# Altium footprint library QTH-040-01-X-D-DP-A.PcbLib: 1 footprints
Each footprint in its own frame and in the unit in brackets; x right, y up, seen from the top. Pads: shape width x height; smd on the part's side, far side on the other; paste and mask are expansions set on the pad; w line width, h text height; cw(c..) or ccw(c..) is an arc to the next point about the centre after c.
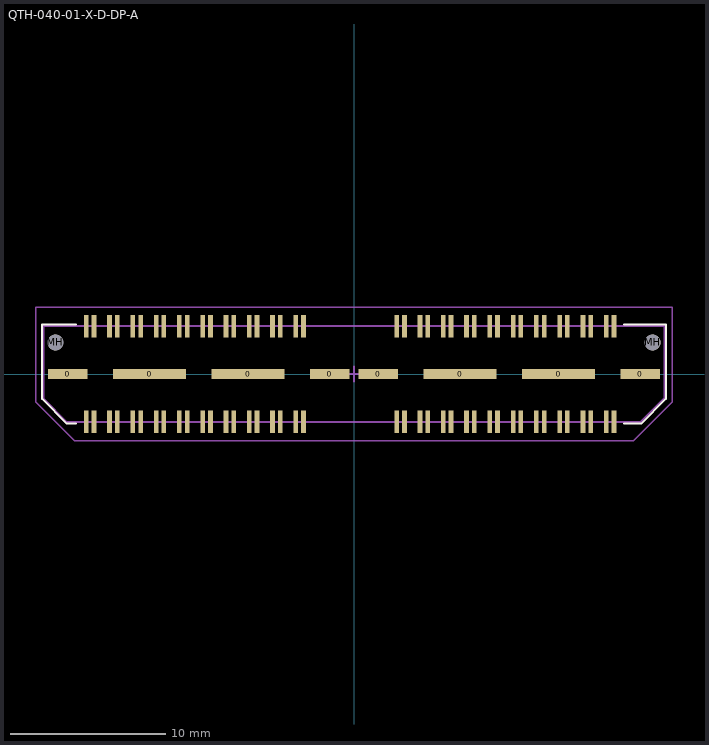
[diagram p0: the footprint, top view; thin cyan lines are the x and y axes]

## QTH-040-01-X-D-DP-A [mm] "0.5mm hi-speed, high-density header (female), 80-pin, non-latching, ground protection in middle"
height 4.06
pads (90):
  rect 2.54x0.64 smd: 0(-18.44,0) 0(-1.56,0) 0(1.56,0) 0(18.44,0)
  rect 4.7x0.64 smd: 0(-13.17,0) 0(-6.82,0) 0(6.83,0) 0(13.18,0)
  rect 0.3x1.45 smd: 1(-17.25,3.09) 2(-17.25,-3.09) 3(-16.75,3.09) 4(-16.75,-3.09) 5(-15.75,3.09) 6(-15.75,-3.09) 7(-15.25,3.09) 8(-15.25,-3.09) 9(-14.25,3.09) 10(-14.25,-3.09) 11(-13.75,3.09) 12(-13.75,-3.09) 13(-12.75,3.09) 14(-12.75,-3.09) 15(-12.25,3.09) 16(-12.25,-3.09) 17(-11.25,3.09) 18(-11.25,-3.09) 19(-10.75,3.09) 20(-10.75,-3.09) 21(-9.75,3.09) 22(-9.75,-3.09) 23(-9.25,3.09) 24(-9.25,-3.09) 25(-8.25,3.09) 26(-8.25,-3.09) 27(-7.75,3.09) 28(-7.75,-3.09) 29(-6.75,3.09) 30(-6.75,-3.09) 31(-6.25,3.09) 32(-6.25,-3.09) 33(-5.25,3.09) 34(-5.25,-3.09) 35(-4.75,3.09) 36(-4.75,-3.09) 37(-3.75,3.09) 38(-3.75,-3.09) 39(-3.25,3.09) 40(-3.25,-3.09) 41(2.75,3.09) 42(2.75,-3.09) 43(3.25,3.09) 44(3.25,-3.09) 45(4.25,3.09) 46(4.25,-3.09) 47(4.75,3.09) 48(4.75,-3.09) 49(5.75,3.09) 50(5.75,-3.09) 51(6.25,3.09) 52(6.25,-3.09) 53(7.25,3.09) 54(7.25,-3.09) 55(7.75,3.09) 56(7.75,-3.09) 57(8.75,3.09) 58(8.75,-3.09) 59(9.25,3.09) 60(9.25,-3.09) 61(10.25,3.09) 62(10.25,-3.09) 63(10.75,3.09) 64(10.75,-3.09) 65(11.75,3.09) 66(11.75,-3.09) 67(12.25,3.09) 68(12.25,-3.09) 69(13.25,3.09) 70(13.25,-3.09) 71(13.75,3.09) 72(13.75,-3.09) 73(14.75,3.09) 74(14.75,-3.09) 75(15.25,3.09) 76(15.25,-3.09) 77(16.25,3.09) 78(16.25,-3.09) 79(16.75,3.09) 80(16.75,-3.09)
  round 1.02 hole 1.02 unplated paste+0: MH(-19.24,2.03) MH(19.24,2.03)
Top Overlay:
  lines w0.12: -17.9,-3.2 -18.5,-3.2 -20.1,-1.6 -20.1,3.2 -17.9,3.2 ; 17.4,-3.2 18.5,-3.2 20.1,-1.6 20.1,3.2 17.4,3.2
Mechanical 15:
  lines w0.1: -0.5,0 0.5,0 ; 0,-0.5 0,0.5 ; -20.5,-1.8 -20.5,4.3 20.5,4.3 20.5,-1.8 18,-4.3 -18,-4.3 -20.5,-1.8
Mechanical 29:
  lines w0.127: -20.005,-1.595 -18.5,-3.1 18.46,-3.1 20.005,-1.555 20.005,3.1 -20.005,3.1 -20.005,-1.595
  text ".Designator" at -1.8,-0.6 h1.27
